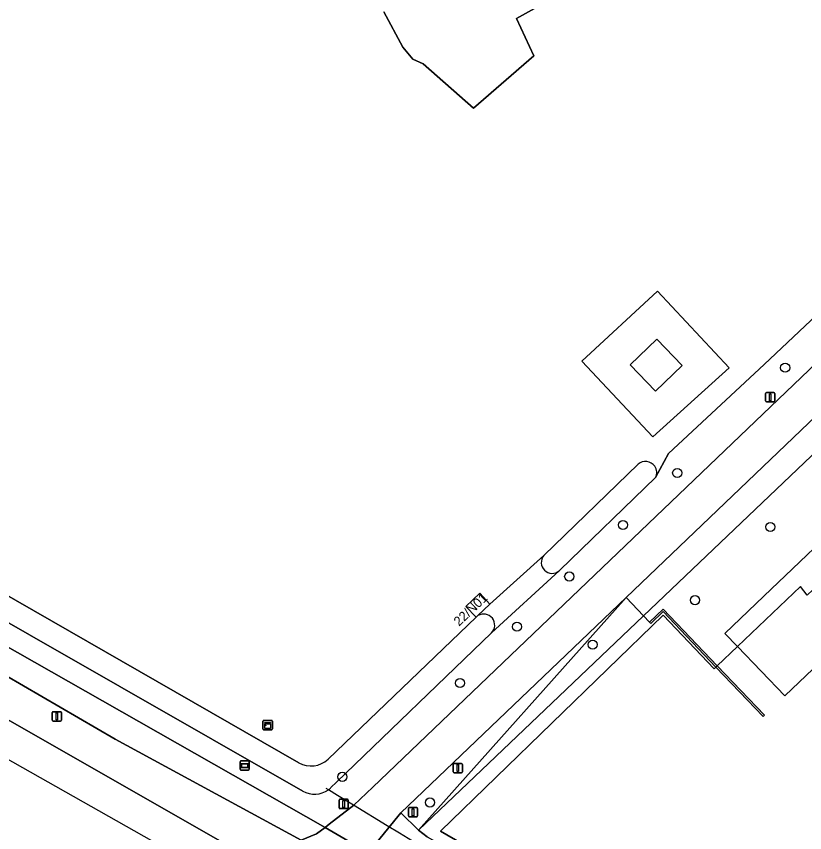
# Model space of a CAD drawing. Extents: x 157132 to 159279, y 384991 to 386650.
# Drawn here: x 157400.4 to 157484.6, y 385940.6 to 386027.8 of the extents above; entities that cross this region are included whole.
import ezdxf

# ---------------------------------------------------------------- set-up
doc = ezdxf.new("R2010")
doc.units = 0
for name, color, linetype in [('IMGEO_Berm_groen', 7, 'Continuous'), ('IMGEO_Boom', 7, 'Continuous'), ('IMGEO_Duiker', 7, 'Continuous'), ('IMGEO_Erf', 7, 'Continuous'), ('IMGEO_Gemengd_bos', 7, 'Continuous'), ('IMGEO_Groenvoorziening', 7, 'Continuous'), ('IMGEO_Hek', 7, 'Continuous'), ('IMGEO_Kast', 7, 'Continuous'), ('IMGEO_Lichtmast', 7, 'Continuous'), ('IMGEO_Loofbos', 7, 'Continuous'), ('IMGEO_Muur', 7, 'Continuous'), ('IMGEO_Pand', 7, 'Continuous'), ('IMGEO_Pand_nummerreeks', 7, 'Continuous'), ('IMGEO_Rijbaan_lokaal_gesloten', 7, 'Continuous'), ('IMGEO_Rijbaan_lokaal_halfverhard', 7, 'Continuous'), ('IMGEO_Rijbaan_lokaal_open', 7, 'Continuous'), ('IMGEO_Verkeersbordpaal', 7, 'Continuous'), ('IMGEO_Verklikker', 7, 'Continuous'), ('IMGEO_Voetpad_open', 7, 'Continuous'), ('IMGEO_Waterloop', 7, 'Continuous')]:
    doc.layers.add(name, color=color, linetype=linetype)

msp = doc.modelspace()

# ---------------------------------------------------------------- linework, layer by layer
at = {"layer": 'IMGEO_Berm_groen'}
msp.add_lwpolyline([(157444.265, 385940.135), (157443.322, 385940.844), (157441.44, 385942.692), (157438.938, 385939.629), (157438.461, 385938.598), (157438.311, 385938.255), (157463.354, 385923.543), (157510.582, 385896.66), (157634.811, 385826.585), (157637.967, 385829.64), (157635.587, 385831.007), (157635.283, 385830.711)], dxfattribs=at)
at = {"layer": 'IMGEO_Boom'}
for centre in [(157482.468, 385990.234), (157470.95, 385979), (157465.159, 385973.45), (157480.886, 385973.228), (157459.424, 385967.939), (157472.851, 385965.418), (157453.843, 385962.579), (157461.917, 385960.668), (157447.772, 385956.565), (157435.199, 385946.549), (157444.556, 385943.809)]:
    msp.add_circle(centre, 0.489, dxfattribs=at)
at = {"layer": 'IMGEO_Duiker'}
msp.add_lwpolyline([(157443.181, 385939.391), (157442.704, 385939.682), (157441.295, 385940.541), (157439.994, 385941.335), (157436.403, 385943.524), (157434.686, 385944.571), (157433.71, 385945.167), (157433.472, 385945.312)], dxfattribs=at)
at = {"layer": 'IMGEO_Erf'}
msp.add_lwpolyline([(157439.639, 386028.238), (157441.67, 386024.453), (157442.745, 386023.194), (157443.83, 386022.672), (157449.187, 386017.948), (157455.643, 386023.546), (157453.792, 386027.519), (157465.26, 386033.93)], dxfattribs=at)
for points in [[(157476.481, 385990.213), (157468.846, 385998.391), (157460.775, 385990.93), (157468.335, 385982.855)], [(157468.616, 385987.736), (157465.919, 385990.545), (157468.769, 385993.281), (157471.466, 385990.472)], [(157499.106, 385984.493), (157495.44, 385988.123), (157494.212, 385989.341), (157467.357, 385963.748), (157468.002, 385963.08), (157468.138, 385962.94), (157469.442, 385964.188), (157475.085, 385958.269), (157474.897, 385958.09), (157469.449, 385963.807), (157445.666, 385940.765), (157512.604, 385902.065), (157541.982, 385942.045), (157539.907, 385944.099)]]:
    msp.add_lwpolyline(points, close=True, dxfattribs=at)
at = {"layer": 'IMGEO_Gemengd_bos'}
msp.add_lwpolyline([(157598.901, 385996.269), (157574.273, 385974.358), (157562.898, 385964.41), (157553.947, 385956.529), (157539.907, 385944.099), (157541.982, 385942.045), (157512.604, 385902.065), (157445.666, 385940.765), (157469.449, 385963.807), (157474.897, 385958.09), (157475.085, 385958.269), (157469.442, 385964.188), (157468.138, 385962.94), (157468.002, 385963.08), (157467.357, 385963.748), (157443.322, 385940.844), (157444.265, 385940.135), (157500, 385908.46), (157548.847, 385880.702), (157597.282, 385853.178)], dxfattribs=at)
at = {"layer": 'IMGEO_Groenvoorziening'}
for points in [[(157211.813, 386074.459), (157213.455, 386068.269), (157211.584, 386069.378), (157211.868, 386068.539), (157226.554, 386059.046), (157238.009, 386052.551), (157275.38, 386031.646), (157325.103, 386002.936), (157371.945, 385976.04), (157409.604, 385954.653), (157433.37, 385941.158), (157433.813, 385941.484), (157436.419, 385943.526), (157438.462, 385945.457), (157516.035, 386019.65)], [(157218.68, 386055.751), (157223.146, 386053.173), (157245.836, 386040.446), (157301.73, 386008.654), (157378.005, 385964.93), (157425.698, 385937.7), (157430.247, 385939.57), (157430.817, 385939.804), (157410.945, 385950.563), (157358.101, 385981.339), (157315.935, 386005.591), (157238.945, 386049.872), (157225.515, 386057.596), (157213.468, 386063.287)], [(157514.492, 386022.88), (157480.247, 385990.585), (157470.001, 385981.062), (157468.646, 385978.498), (157458.434, 385968.621), (157458.397, 385968.586), (157458.359, 385968.552), (157451.132, 385961.918), (157434.589, 385945.977), (157433.992, 385945.402)], [(157430.993, 385945.025), (157382.245, 385972.899), (157335.454, 386000), (157327.314, 386004.599), (157301.157, 386019.377)], [(157456.7, 385970.177), (157450.963, 385965.003), (157449.675, 385963.768)], [(157451.132, 385961.918), (157458.359, 385968.552)]]:
    msp.add_lwpolyline(points, dxfattribs=at)
for points in [[(157465.486, 385965.685), (157441.44, 385942.692), (157443.322, 385940.844)], [(157465.486, 385965.685), (157443.322, 385940.844), (157467.357, 385963.748)]]:
    msp.add_lwpolyline(points, close=True, dxfattribs=at)
for centre, radius, start, end in [((157457.609, 385969.445), 1.167, 141.15026, 310.03609), ((157450.282, 385962.747), 1.188, 315.70582, 120.73982), ((157432.241, 385947.209), 2.516, 240.25749, 305.72602), ((157432.264, 385947.189), 2.486, 305.57074, 314.0404)]:
    msp.add_arc(centre, radius, start, end, dxfattribs=at)
at = {"layer": 'IMGEO_Hek'}
for points in [[(157468.335, 385982.855), (157460.775, 385990.93), (157468.846, 385998.391), (157476.481, 385990.213), (157468.335, 385982.855)], [(157486.65, 385967.671), (157484.834, 385965.963), (157484.117, 385966.862), (157477.388, 385960.46)], [(157475.085, 385958.269), (157474.897, 385958.09), (157469.449, 385963.807), (157445.666, 385940.765), (157512.604, 385902.065), (157541.982, 385942.045), (157539.907, 385944.099)], [(157477.388, 385960.46), (157475.23, 385958.407)], [(157475.23, 385958.407), (157475.085, 385958.269)]]:
    msp.add_lwpolyline(points, dxfattribs=at)
at = {"layer": 'IMGEO_Kast'}
for p, q in [((157426.735, 385951.655), (157426.735, 385952.496)), ((157426.735, 385952.496), (157426.735, 385951.655)), ((157426.81, 385952.58), (157427.651, 385952.58)), ((157427.651, 385952.58), (157426.81, 385952.58)), ((157427.735, 385952.505), (157427.735, 385951.664)), ((157427.735, 385951.664), (157427.735, 385952.505)), ((157427.66, 385951.58), (157426.819, 385951.58)), ((157426.819, 385951.58), (157427.66, 385951.58))]:
    msp.add_line(p, q, dxfattribs=at)
for points in [[(157426.93, 385952.37), (157427.53, 385952.37), (157427.53, 385952.285), (157426.93, 385952.285), (157426.93, 385952.37)], [(157426.93, 385952.195), (157427.53, 385952.195), (157427.53, 385951.706), (157426.93, 385951.706), (157426.93, 385952.195)]]:
    msp.add_lwpolyline(points, dxfattribs=at)
msp.add_circle((157427.014, 385952.044), 0.0377, dxfattribs=at)
for centre, start, end in [((157426.813, 385952.502), 92.4484, 184.28452), ((157426.813, 385952.502), 92.4484, 184.28452), ((157427.657, 385952.502), 2.4484, 94.28452), ((157427.657, 385952.502), 2.4484, 94.28452), ((157426.813, 385951.658), 182.4484, 274.28452), ((157426.813, 385951.658), 182.4484, 274.28452), ((157427.657, 385951.658), 272.4484, 4.28452), ((157427.657, 385951.658), 272.4484, 4.28452)]:
    msp.add_arc(centre, 0.0779, start, end, dxfattribs=at)
at = {"layer": 'IMGEO_Lichtmast'}
for p, q in [((157480.468, 385987.589), (157481.258, 385987.589)), ((157481.258, 385987.589), (157480.468, 385987.589)), ((157480.368, 385986.689), (157480.368, 385987.489)), ((157480.368, 385987.489), (157480.368, 385986.689)), ((157481.358, 385987.489), (157481.358, 385986.689)), ((157481.358, 385986.689), (157481.358, 385987.489)), ((157481.258, 385986.589), (157480.468, 385986.589)), ((157480.468, 385986.589), (157481.258, 385986.589)), ((157404.222, 385952.606), (157404.222, 385953.406)), ((157404.222, 385953.406), (157404.222, 385952.606)), ((157404.322, 385953.506), (157405.112, 385953.506)), ((157405.112, 385953.506), (157404.322, 385953.506)), ((157405.212, 385953.406), (157405.212, 385952.606)), ((157405.212, 385952.606), (157405.212, 385953.406)), ((157405.112, 385952.506), (157404.322, 385952.506)), ((157404.322, 385952.506), (157405.112, 385952.506))]:
    msp.add_line(p, q, dxfattribs=at)
for points in [[(157480.788, 385987.464), (157480.938, 385987.464), (157480.938, 385986.714), (157480.788, 385986.714), (157480.788, 385987.464)], [(157404.642, 385953.381), (157404.792, 385953.381), (157404.792, 385952.631), (157404.642, 385952.631), (157404.642, 385953.381)]]:
    msp.add_lwpolyline(points, dxfattribs=at)
for centre, start, end in [((157480.468, 385987.489), 90, 180), ((157480.468, 385987.489), 90, 180), ((157481.258, 385987.489), 0, 90), ((157481.258, 385987.489), 360, 90), ((157480.468, 385986.689), 180, 270), ((157480.468, 385986.689), 180, 270), ((157481.258, 385986.689), 270, 0), ((157481.258, 385986.689), 270, 0), ((157404.322, 385953.406), 90, 180), ((157404.322, 385953.406), 90, 180), ((157405.112, 385953.406), 0, 90), ((157405.112, 385953.406), 360, 90), ((157404.322, 385952.606), 180, 270), ((157404.322, 385952.606), 180, 270), ((157405.112, 385952.606), 270, 0), ((157405.112, 385952.606), 270, 0)]:
    msp.add_arc(centre, 0.1, start, end, dxfattribs=at)
at = {"layer": 'IMGEO_Loofbos'}
for points in [[(157465.26, 386033.93), (157453.792, 386027.519), (157455.643, 386023.546), (157449.187, 386017.948), (157443.83, 386022.672), (157442.745, 386023.194), (157441.67, 386024.453), (157439.639, 386028.238)], [(157468.646, 385978.498), (157470.001, 385981.062), (157480.247, 385990.585), (157514.492, 386022.88), (157513.318, 386023.647), (157512.054, 386024.46), (157508.126, 386025.634), (157503.116, 386026.834), (157500, 386027.379), (157488.172, 386029.446)], [(157300.635, 386022.932), (157328.537, 386006.698), (157340.049, 386000), (157430.563, 385948.058)], [(157433.678, 385948.439), (157449.482, 385963.583), (157448.383, 385964.741), (157449.864, 385966.168), (157450.963, 385965.003), (157456.7, 385970.177), (157466.785, 385979.939)]]:
    msp.add_lwpolyline(points, dxfattribs=at)
msp.add_lwpolyline([(157476.481, 385990.213), (157468.335, 385982.855), (157460.775, 385990.93), (157468.846, 385998.391)], close=True, dxfattribs=at)
for centre, radius, start, end in [((157467.562, 385979.021), 1.203, 35.00537, 130.25688), ((157467.565, 385979.021), 1.201, 334.1783, 35.05965), ((157431.867, 385950.324), 2.614, 240.08165, 313.86493)]:
    msp.add_arc(centre, radius, start, end, dxfattribs=at)
at = {"layer": 'IMGEO_Muur'}
for points in [[(157487.906, 385973.193), (157482.488, 385968.012)], [(157482.488, 385968.012), (157481.01, 385966.64)], [(157481.01, 385966.64), (157476.042, 385961.862)], [(157468.002, 385963.08), (157469.458, 385964.466), (157475.23, 385958.407)], [(157475.085, 385958.269), (157469.442, 385964.188), (157468.138, 385962.94), (157468.002, 385963.08)], [(157477.388, 385960.46), (157482.442, 385955.19), (157485.449, 385958.076), (157485.765, 385957.731), (157490.578, 385962.391)], [(157476.042, 385961.862), (157477.388, 385960.46)], [(157475.23, 385958.407), (157480.256, 385953.133), (157480.117, 385952.99), (157475.085, 385958.269)]]:
    msp.add_lwpolyline(points, dxfattribs=at)
at = {"layer": 'IMGEO_Pand'}
for points in [[(157468.616, 385987.736), (157471.466, 385990.472), (157468.769, 385993.281), (157465.919, 385990.545)], [(157449.482, 385963.583), (157449.675, 385963.768), (157450.963, 385965.003), (157449.864, 385966.168), (157448.383, 385964.741)]]:
    msp.add_lwpolyline(points, close=True, dxfattribs=at)
at = {"layer": 'IMGEO_Rijbaan_lokaal_gesloten'}
msp.add_lwpolyline([(157423.997, 385934.57), (157425.698, 385937.7), (157378.005, 385964.93), (157301.73, 386008.654), (157245.836, 386040.446), (157243.665, 386036.662)], close=True, dxfattribs=at)
at = {"layer": 'IMGEO_Rijbaan_lokaal_halfverhard'}
msp.add_lwpolyline([(157494.212, 385989.341), (157492.254, 385991.281), (157465.486, 385965.685), (157467.357, 385963.748)], close=True, dxfattribs=at)
at = {"layer": 'IMGEO_Rijbaan_lokaal_open'}
for points in [[(157534.38, 386031.563), (157540.478, 386037.394), (157593.703, 386088.289), (157605.005, 386099.141), (157605.131, 386099.144), (157608.163, 386102.263), (157605.479, 386105.148), (157600.572, 386099.835), (157599.534, 386099.492), (157595.681, 386095.825), (157524.001, 386027.268), (157516.035, 386019.65), (157438.462, 385945.457), (157436.419, 385943.526), (157433.813, 385941.484), (157433.37, 385941.158), (157438.311, 385938.255), (157438.461, 385938.598), (157438.938, 385939.629), (157441.44, 385942.692), (157465.486, 385965.685), (157492.254, 385991.281)], [(157438.311, 385938.255), (157433.37, 385941.158), (157432.429, 385940.467), (157430.817, 385939.804), (157430.247, 385939.57), (157425.698, 385937.7), (157437.498, 385930.964), (157437.501, 385935.475), (157437.493, 385936.381)]]:
    msp.add_lwpolyline(points, close=True, dxfattribs=at)
at = {"layer": 'IMGEO_Verkeersbordpaal'}
for p, q in [((157447.049, 385947.08), (157447.049, 385947.88)), ((157447.049, 385947.88), (157447.049, 385947.08)), ((157447.149, 385947.98), (157447.939, 385947.98)), ((157447.939, 385947.98), (157447.149, 385947.98)), ((157448.039, 385947.88), (157448.039, 385947.08)), ((157448.039, 385947.08), (157448.039, 385947.88)), ((157447.939, 385946.98), (157447.149, 385946.98)), ((157447.149, 385946.98), (157447.939, 385946.98)), ((157434.849, 385943.258), (157434.849, 385944.058)), ((157434.849, 385944.058), (157434.849, 385943.258)), ((157434.949, 385944.158), (157435.739, 385944.158)), ((157435.739, 385944.158), (157434.949, 385944.158)), ((157435.839, 385944.058), (157435.839, 385943.258)), ((157435.839, 385943.258), (157435.839, 385944.058)), ((157435.739, 385943.158), (157434.949, 385943.158)), ((157434.949, 385943.158), (157435.739, 385943.158)), ((157442.253, 385942.373), (157442.253, 385943.173)), ((157442.253, 385943.173), (157442.253, 385942.373)), ((157442.353, 385943.273), (157443.143, 385943.273)), ((157443.143, 385943.273), (157442.353, 385943.273)), ((157443.243, 385943.173), (157443.243, 385942.373)), ((157443.243, 385942.373), (157443.243, 385943.173)), ((157443.143, 385942.273), (157442.353, 385942.273)), ((157442.353, 385942.273), (157443.143, 385942.273))]:
    msp.add_line(p, q, dxfattribs=at)
for points in [[(157447.469, 385947.855), (157447.619, 385947.855), (157447.619, 385947.105), (157447.469, 385947.105), (157447.469, 385947.855)], [(157435.269, 385944.033), (157435.419, 385944.033), (157435.419, 385943.283), (157435.269, 385943.283), (157435.269, 385944.033)], [(157442.673, 385943.148), (157442.823, 385943.148), (157442.823, 385942.398), (157442.673, 385942.398), (157442.673, 385943.148)]]:
    msp.add_lwpolyline(points, dxfattribs=at)
for centre, start, end in [((157447.149, 385947.88), 90, 180), ((157447.149, 385947.88), 90, 180), ((157447.939, 385947.88), 0, 90), ((157447.939, 385947.88), 360, 90), ((157447.149, 385947.08), 180, 270), ((157447.149, 385947.08), 180, 270), ((157447.939, 385947.08), 270, 0), ((157447.939, 385947.08), 270, 0), ((157434.949, 385944.058), 90, 180), ((157434.949, 385944.058), 90, 180), ((157435.739, 385944.058), 0, 90), ((157435.739, 385944.058), 360, 90), ((157434.949, 385943.258), 180, 270), ((157434.949, 385943.258), 180, 270), ((157435.739, 385943.258), 270, 0), ((157435.739, 385943.258), 270, 0), ((157442.353, 385943.173), 90, 180), ((157442.353, 385943.173), 90, 180), ((157443.143, 385943.173), 0, 90), ((157443.143, 385943.173), 360, 90), ((157442.353, 385942.373), 180, 270), ((157442.353, 385942.373), 180, 270), ((157443.143, 385942.373), 270, 0), ((157443.143, 385942.373), 270, 0)]:
    msp.add_arc(centre, 0.1, start, end, dxfattribs=at)
at = {"layer": 'IMGEO_Verklikker'}
for p, q in [((157424.285, 385947.353), (157424.285, 385948.153)), ((157424.285, 385948.153), (157424.285, 385947.353)), ((157424.385, 385948.253), (157425.175, 385948.253)), ((157425.175, 385948.253), (157424.385, 385948.253)), ((157425.275, 385948.153), (157425.275, 385947.353)), ((157425.275, 385947.353), (157425.275, 385948.153)), ((157425.175, 385947.253), (157424.385, 385947.253)), ((157424.385, 385947.253), (157425.175, 385947.253))]:
    msp.add_line(p, q, dxfattribs=at)
for points in [[(157424.386, 385947.985), (157425.174, 385947.985), (157425.174, 385947.521), (157424.386, 385947.521), (157424.386, 385947.985)], [(157424.451, 385947.92), (157424.451, 385947.586), (157425.109, 385947.586), (157425.109, 385947.92), (157424.451, 385947.92)]]:
    msp.add_lwpolyline(points, dxfattribs=at)
for centre, start, end in [((157424.385, 385948.153), 90, 180), ((157424.385, 385948.153), 90, 180), ((157425.175, 385948.153), 0, 90), ((157425.175, 385948.153), 360, 90), ((157424.385, 385947.353), 180, 270), ((157424.385, 385947.353), 180, 270), ((157425.175, 385947.353), 270, 0), ((157425.175, 385947.353), 270, 0)]:
    msp.add_arc(centre, 0.1, start, end, dxfattribs=at)
at = {"layer": 'IMGEO_Voetpad_open'}
msp.add_lwpolyline([(157211.868, 386068.539), (157212.531, 386065.943), (157213.468, 386063.287), (157225.515, 386057.596), (157238.945, 386049.872), (157315.935, 386005.591), (157358.101, 385981.339), (157410.945, 385950.563), (157430.817, 385939.804), (157432.429, 385940.467), (157433.37, 385941.158), (157409.604, 385954.653), (157371.945, 385976.04), (157325.103, 386002.936), (157275.38, 386031.646), (157238.009, 386052.551), (157226.554, 386059.046)], close=True, dxfattribs=at)
at = {"layer": 'IMGEO_Waterloop'}
for points in [[(157430.563, 385948.058), (157340.049, 386000), (157328.537, 386006.698), (157300.635, 386022.932)], [(157301.157, 386019.377), (157327.314, 386004.599), (157335.454, 386000), (157382.245, 385972.899), (157430.993, 385945.025)], [(157466.785, 385979.939), (157456.7, 385970.177)], [(157458.359, 385968.552), (157458.397, 385968.586), (157458.434, 385968.621), (157468.646, 385978.498)], [(157449.675, 385963.768), (157449.482, 385963.583), (157433.678, 385948.439)], [(157433.992, 385945.402), (157434.589, 385945.977), (157451.132, 385961.918)]]:
    msp.add_lwpolyline(points, dxfattribs=at)
for centre, radius, start, end in [((157467.562, 385979.021), 1.203, 35.00537, 130.25688), ((157467.565, 385979.021), 1.201, 334.1783, 35.05965), ((157457.609, 385969.445), 1.167, 141.15026, 310.03609), ((157450.282, 385962.747), 1.188, 315.70582, 120.73982), ((157431.867, 385950.324), 2.614, 240.08165, 313.86493), ((157432.241, 385947.209), 2.516, 240.25749, 305.72602), ((157432.264, 385947.189), 2.486, 305.57074, 314.0404)]:
    msp.add_arc(centre, radius, start, end, dxfattribs=at)

# ---------------------------------------------------------------- texts
at = {"layer": 'IMGEO_Pand_nummerreeks'}
msp.add_text('22/N01', height=1, rotation=43.38013, dxfattribs=at).set_placement((157447.661, 385962.584))

doc.saveas('drawing.dxf')
